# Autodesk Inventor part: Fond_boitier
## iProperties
Created: 2011-07
Part Number: Fond_boitier
Document SubType Name: Modeling
Designer: domi
Density: 1 g/cm^3
Author: domi
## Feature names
1. Corps [Extrusion]
2. Complement corps [Extrusion]
3. Chanfrein 1 [Extrusion]
4. Arrondi1 [Extrusion]
5. Congé1 [Fillet]
6. Chanfein2 [Extrusion]
7. Suite chanfrein2 [Extrusion]
8. Arrondi2 [Extrusion]
9. Coque
10. Epaulement Languette [Extrusion]
11. Non languette [Extrusion]
12. Bossage inter_1 [Extrusion]
13. Bossage exter_1 [Extrusion]
14. Trou lamé inter_1 [Extrusion]
15. Trou lamé exter_1 [Hole]
